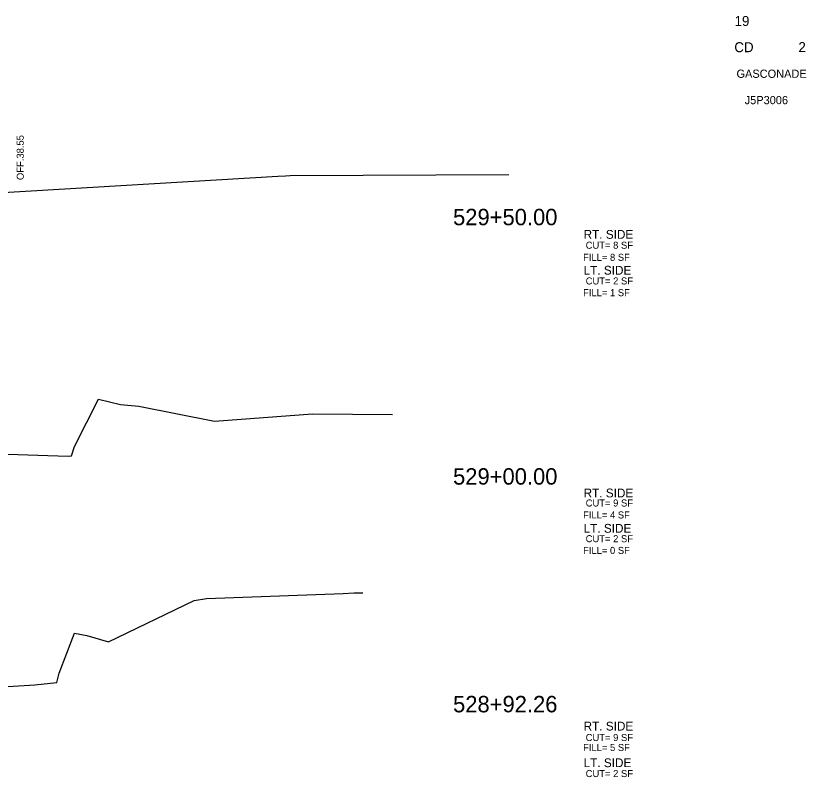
# Model space of a CAD drawing. Extents: x -4 to 359, y 0 to 1436.
# Drawn here: x 86.8 to 154.2, y 171.2 to 236.1 of the extents above; entities that cross this region are included whole.
import ezdxf

# ---------------------------------------------------------------- set-up
doc = ezdxf.new("R2010")
doc.units = 0
for name, color, linetype in [('Common-Title block info', 7, 'Continuous'), ('XS-Existing surface-ground', 7, 'Continuous'), ('XS-Text-earthwork labels', 7, 'Continuous'), ('XS-Text-offset label', 7, 'Continuous'), ('XS-Text-tie elevation', 7, 'Continuous')]:
    doc.layers.add(name, color=color, linetype=linetype)

msp = doc.modelspace()

# ---------------------------------------------------------------- linework, layer by layer
at = {"layer": 'XS-Existing surface-ground'}
for p, q in [((109.093, 222.41), (109.736, 222.447)), ((109.736, 222.447), (110.135, 222.471)), ((110.135, 222.471), (128.783, 222.542)), ((83.188, 220.869), (109.093, 222.41)), ((91.757, 199.355), (93.816, 203.396)), ((93.816, 203.396), (95.679, 202.947)), ((95.679, 202.947), (97.255, 202.797)), ((97.255, 202.797), (103.697, 201.523)), ((103.697, 201.523), (112.043, 202.134)), ((112.043, 202.134), (118.868, 202.078)), ((91.508, 198.549), (91.757, 199.355)), ((82.17, 198.812), (91.223, 198.533)), ((91.223, 198.533), (91.508, 198.549)), ((103.026, 186.392), (114.659, 186.805)), ((114.659, 186.805), (115.595, 186.876)), ((115.595, 186.876), (116.358, 186.871)), ((94.651, 182.703), (101.952, 186.217)), ((101.952, 186.217), (103.026, 186.392)), ((90.462, 180.023), (91.745, 183.422)), ((91.745, 183.422), (92.795, 183.234)), ((92.795, 183.234), (94.651, 182.703)), ((90.237, 179.229), (90.462, 180.023)), ((86.072, 178.889), (88.361, 179.034)), ((88.361, 179.034), (90.237, 179.229))]:
    msp.add_line(p, q, dxfattribs=at)

# ---------------------------------------------------------------- texts
at = {"layer": 'Common-Title block info'}
for s, height, p in [('19', 0.85, (148.047, 235.221)), ('CD', 0.85, (148.025, 232.983)), ('2', 0.85, (153.492, 232.988)), ('GASCONADE', 0.7, (148.211, 230.796)), ('J5P3006', 0.7, (148.909, 228.546))]:
    msp.add_text(s, height=height, dxfattribs=at).set_placement(p)
at = {"layer": 'XS-Text-earthwork labels'}
for s, height, p in [('RT. SIDE', 0.75, (135.171, 217.068)), (' CUT= 8 SF           ', 0.6, (135.125, 216.218)), ('FILL= 8 SF           ', 0.6, (135.125, 215.186)), ('LT. SIDE', 0.75, (135.171, 214.009)), (' CUT= 2 SF           ', 0.6, (135.125, 213.173)), ('FILL= 1 SF           ', 0.6, (135.125, 212.172)), ('RT. SIDE', 0.75, (135.171, 195.015)), (' CUT= 9 SF           ', 0.6, (135.125, 194.236)), ('FILL= 4 SF           ', 0.6, (135.125, 193.215)), ('LT. SIDE', 0.75, (135.171, 192.002)), (' CUT= 2 SF           ', 0.6, (135.125, 191.191)), ('FILL= 0 SF           ', 0.6, (135.125, 190.193)), ('RT. SIDE', 0.75, (135.171, 175.134)), (' CUT= 9 SF           ', 0.6, (135.125, 174.236)), ('FILL= 5 SF           ', 0.6, (135.125, 173.384)), ('LT. SIDE', 0.75, (135.171, 172.008)), (' CUT= 2 SF           ', 0.6, (135.125, 171.161))]:
    msp.add_text(s, height=height, dxfattribs=at).set_placement(p)
at = {"layer": 'XS-Text-offset label'}
for s, p in [('           529+50.00           ', (118.317, 218.222)), ('           529+00.00           ', (118.317, 196.102)), ('           528+92.26           ', (118.317, 176.684))]:
    msp.add_text(s, height=1.4, dxfattribs=at).set_placement(p)
at = {"layer": 'XS-Text-tie elevation'}
msp.add_text('OFF.38.55', height=0.6, rotation=90, dxfattribs=at).set_placement((87.428, 222.077))

doc.saveas('drawing.dxf')
